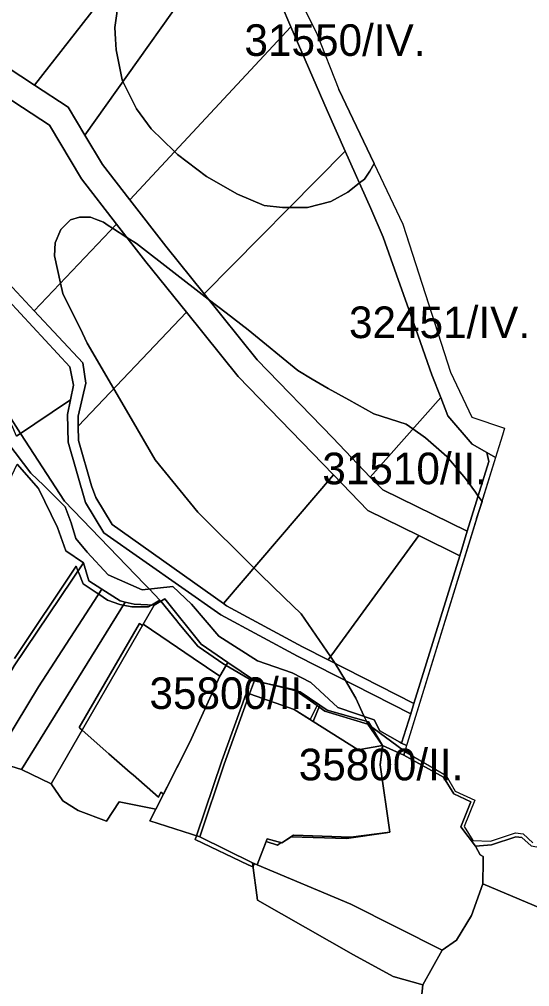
# Model space of a CAD drawing. Extents: x -522079 to -518792, y -1142400 to -1139961.
# Drawn here: x -519685.2 to -519443.2, y -1141371.1 to -1140912.1 of the extents above; entities that cross this region are included whole.
import ezdxf

# ---------------------------------------------------------------- set-up
doc = ezdxf.new("R2010")
doc.units = 0
for name, color, linetype in [('Hranice parcel', 7, 'Continuous'), ('Parcelní čísla', 7, 'Continuous'), ('Poz předměty', 7, 'Continuous'), ('Vnitřní kresba', 7, 'Continuous'), ('Značky bodu BP', 7, 'Continuous'), ('Značky budov', 7, 'Continuous'), ('Značky kultur', 7, 'Continuous')]:
    doc.layers.add(name, color=color, linetype=linetype)

msp = doc.modelspace()

# ---------------------------------------------------------------- linework, layer by layer
at = {"layer": 'Hranice parcel'}
for points in [[(-519569.14, -1140869.38), (-519544.31, -1140918.54), (-519533.66, -1140945.39), (-519503.31, -1141009.21), (-519480.71, -1141079.48), (-519470.66, -1141100.87), (-519455.06, -1141106.14), (-519456.05, -1141109.33), (-519457.77, -1141114.91), (-519459.37, -1141120.07), (-519463.51, -1141117.64), (-519470.4, -1141113.6), (-519481.95, -1141100.21), (-519485.33, -1141091.52), (-519489.53, -1141080.75), (-519497.19, -1141059.15), (-519506.32, -1141033.4), (-519512.69, -1141015.45), (-519518.48, -1141001.84), (-519530.67, -1140974.63), (-519539.28, -1140955.41), (-519556.41, -1140915.6), (-519561.03, -1140904.86)], [(-519697.68, -1140930.5), (-519678.04, -1140943.34), (-519662.03, -1140953.81), (-519654.13, -1140967.02), (-519645.74, -1140981.03), (-519632.87, -1140997.67), (-519615.79, -1141019.75), (-519597.55, -1141042.38), (-519572.39, -1141073.59), (-519536.59, -1141110.65), (-519518.89, -1141129.28), (-519512.81, -1141135.27), (-519472.79, -1141154.97), (-519476.38, -1141166.58), (-519495.79, -1141157.02), (-519519.99, -1141145.11), (-519536.28, -1141128.25), (-519581.39, -1141081.54), (-519605.96, -1141051.06), (-519625.22, -1141027.17), (-519639.1, -1141009.23), (-519655.67, -1140987.81), (-519670.91, -1140962.34), (-519692.38, -1140948.3)], [(-519704.97, -1141021.67), (-519678.16, -1141050.41), (-519655.12, -1141075.09), (-519653.67, -1141084.78), (-519657.33, -1141100.32), (-519657.23, -1141105.11), (-519657.08, -1141111.95), (-519650.97, -1141133.45), (-519648.88, -1141138.93), (-519641.2, -1141151.84), (-519588.4, -1141189.29), (-519586.93, -1141190.33), (-519550.99, -1141209.75), (-519538.78, -1141215.99), (-519498.1, -1141236.79), (-519499.59, -1141241.58), (-519553.27, -1141214.2), (-519589.6, -1141194.6), (-519645.14, -1141155.67), (-519653.82, -1141141.35), (-519662.06, -1141112.71), (-519662.35, -1141099.54), (-519660.92, -1141092.62), (-519659.49, -1141085.69), (-519661.22, -1141076.98), (-519702.3, -1141032.7)], [(-519686.59, -1141109.94), (-519660.92, -1141092.62), (-519662.35, -1141099.54), (-519662.06, -1141112.71), (-519653.82, -1141141.35), (-519645.14, -1141155.67), (-519589.6, -1141194.6), (-519553.27, -1141214.2), (-519499.59, -1141241.58), (-519503.9, -1141255.56), (-519504.82, -1141255.11), (-519514.28, -1141249.74), (-519516.96, -1141244.4), (-519534.2, -1141238.58), (-519546.94, -1141226.78), (-519555.86, -1141222.18), (-519572.33, -1141216.46), (-519590.58, -1141204.82), (-519603.54, -1141189.56), (-519612.48, -1141181.23), (-519626.9, -1141182.72), (-519643.13, -1141175.65), (-519653.03, -1141164.92), (-519658.41, -1141158.35), (-519660.65, -1141151.03), (-519663.4, -1141143.35), (-519673.55, -1141133.3), (-519679.71, -1141127.39), (-519690.7, -1141113)]]:
    msp.add_lwpolyline(points, dxfattribs=at)
msp.add_lwpolyline([(-519524.47, -1141258.63), (-519545.8, -1141245.26), (-519542.77, -1141237.45), (-519539.27, -1141239.84), (-519519.64, -1141245.38), (-519512.96, -1141256.69)], close=True, dxfattribs=at)
at = {"layer": 'Parcelní čísla'}
for points in [[(-519758.42, -1140883.91), (-519698.98, -1140816.54), (-519677.02, -1140829.78), (-519655.55, -1140840.89), (-519633.63, -1140850.83), (-519613.39, -1140860.38), (-519678.04, -1140943.34), (-519697.68, -1140930.5)], [(-519654.13, -1140967.02), (-519587.52, -1140873.31), (-519580.34, -1140878), (-519573.15, -1140884.93), (-519566.48, -1140893.71), (-519561.03, -1140904.86), (-519556.41, -1140915.6), (-519632.87, -1140997.67), (-519645.74, -1140981.03)], [(-519530.67, -1140974.63), (-519597.55, -1141042.38), (-519615.79, -1141019.75), (-519632.87, -1140997.67), (-519556.41, -1140915.6), (-519539.28, -1140955.41)], [(-519692.38, -1140948.3), (-519670.91, -1140962.34), (-519655.67, -1140987.81), (-519639.1, -1141009.23), (-519678.16, -1141050.41), (-519704.97, -1141021.67), (-519737.76, -1141001.71), (-519738.84, -1141001.14)], [(-519597.55, -1141042.38), (-519530.67, -1140974.63), (-519518.48, -1141001.84), (-519512.69, -1141015.45), (-519506.32, -1141033.4), (-519497.19, -1141059.15), (-519489.53, -1141080.75), (-519485.33, -1141091.52), (-519518.89, -1141129.28), (-519536.59, -1141110.65), (-519572.39, -1141073.59)], [(-519678.16, -1141050.41), (-519639.1, -1141009.23), (-519625.22, -1141027.17), (-519605.96, -1141051.06), (-519657.23, -1141105.11), (-519657.33, -1141100.32), (-519653.67, -1141084.78), (-519655.12, -1141075.09)], [(-519605.96, -1141051.06), (-519581.39, -1141081.54), (-519536.28, -1141128.25), (-519588.4, -1141189.29), (-519641.2, -1141151.84), (-519648.88, -1141138.93), (-519650.97, -1141133.45), (-519657.08, -1141111.95), (-519657.23, -1141105.11)], [(-519462.56, -1141121.92), (-519472.79, -1141154.97), (-519512.81, -1141135.27), (-519518.89, -1141129.28), (-519485.33, -1141091.52), (-519481.95, -1141100.21), (-519470.4, -1141113.6), (-519463.51, -1141117.64)], [(-519588.4, -1141189.29), (-519536.28, -1141128.25), (-519519.99, -1141145.11), (-519495.79, -1141157.02), (-519538.78, -1141215.99), (-519550.99, -1141209.75), (-519586.93, -1141190.33)], [(-519476.38, -1141166.58), (-519498.1, -1141236.79), (-519538.78, -1141215.99), (-519495.79, -1141157.02)]]:
    msp.add_lwpolyline(points, close=True, dxfattribs=at)
at = {"layer": 'Poz předměty'}
for points in [[(-519587.52, -1140873.31), (-519654.13, -1140967.02), (-519662.03, -1140953.81), (-519678.04, -1140943.34), (-519613.39, -1140860.38), (-519591.11, -1140871.05)], [(-519555.19, -1141299.24), (-519560.68, -1141302.79), (-519567.64, -1141300.94), (-519572.4, -1141313.2), (-519574.58, -1141312.28), (-519599.57, -1141299.96), (-519588.13, -1141265.46), (-519575.99, -1141232.08), (-519554.92, -1141239.55), (-519545.8, -1141245.26), (-519524.47, -1141258.63), (-519512.96, -1141256.69), (-519514.13, -1141265.79), (-519509.48, -1141297.81), (-519527.97, -1141300.15)]]:
    msp.add_lwpolyline(points, close=True, dxfattribs=at)
at = {"layer": 'Vnitřní kresba'}
for points in [[(-519690.7, -1141113), (-519679.71, -1141127.39), (-519673.55, -1141133.3), (-519663.4, -1141143.35), (-519660.65, -1141151.03), (-519658.41, -1141158.35), (-519653.03, -1141164.92), (-519643.13, -1141175.65), (-519626.9, -1141182.72), (-519612.48, -1141181.23), (-519603.54, -1141189.56), (-519590.58, -1141204.82), (-519572.33, -1141216.46), (-519555.86, -1141222.18), (-519546.94, -1141226.78), (-519534.2, -1141238.58), (-519516.96, -1141244.4), (-519514.28, -1141249.74), (-519504.82, -1141255.11), (-519503.9, -1141255.56), (-519501.64, -1141256.67), (-519502.46, -1141259.44), (-519502.94, -1141261.24), (-519512.96, -1141256.69), (-519519.64, -1141245.38), (-519539.27, -1141239.84), (-519542.77, -1141237.45), (-519552.03, -1141231.12), (-519573.7, -1141225.77), (-519586.25, -1141217.21), (-519599.05, -1141208.49), (-519616.23, -1141186.99), (-519621.3, -1141190.09), (-519630.7, -1141189.62), (-519635, -1141188.59), (-519637.37, -1141188.02), (-519646.01, -1141182.51), (-519652.19, -1141178.57), (-519654.81, -1141169.94), (-519663.19, -1141164.28), (-519667.13, -1141153.28), (-519676.06, -1141134.77), (-519686.19, -1141123.12)], [(-519442.41, -1141304.27), (-519446.9, -1141300.29), (-519449.71, -1141299.98), (-519461.31, -1141303.85), (-519468.94, -1141304.33), (-519475.87, -1141295.24), (-519471.1, -1141283.41), (-519479.21, -1141279.64), (-519484.08, -1141271.62), (-519502.94, -1141261.24), (-519502.46, -1141259.44), (-519482.78, -1141270.88), (-519478.58, -1141278.28), (-519469.18, -1141282.65), (-519474.2, -1141295.1), (-519470.14, -1141301.74), (-519461.74, -1141302), (-519449.98, -1141298.09), (-519446.22, -1141298.48), (-519441.7, -1141302.87)]]:
    msp.add_lwpolyline(points, dxfattribs=at)
msp.add_lwpolyline([(-519462.56, -1141121.92), (-519463.51, -1141117.64), (-519459.37, -1141120.07), (-519501.33, -1141255.67), (-519501.64, -1141256.67), (-519503.9, -1141255.56), (-519499.59, -1141241.58), (-519498.1, -1141236.79), (-519476.38, -1141166.58), (-519472.79, -1141154.97)], close=True, dxfattribs=at)
at = {"layer": 'Značky bodu BP'}
for points in [[(-519569.14, -1140869.38), (-519544.31, -1140918.54), (-519533.66, -1140945.39), (-519516.96, -1140980.51), (-519518.95, -1140984.06), (-519521.57, -1140987.86), (-519523.9, -1140989.74), (-519524.88, -1140990.52), (-519529.4, -1140994.15), (-519537.54, -1140998.54), (-519548.5, -1141001.37), (-519557.07, -1141001.37), (-519560.4, -1141001.37), (-519569.16, -1141000.43), (-519581.69, -1140995.09), (-519596.41, -1140986.61), (-519610.19, -1140976.25), (-519611.61, -1140974.85), (-519622.71, -1140964), (-519629.6, -1140954.57), (-519636.06, -1140941.6), (-519636.49, -1140940.75), (-519639.31, -1140926.61), (-519639.6, -1140921.53), (-519639.93, -1140915.93), (-519638.05, -1140902.43)], [(-519638.05, -1140902.43), (-519639.93, -1140915.93), (-519639.6, -1140921.53), (-519639.31, -1140926.61), (-519636.49, -1140940.75), (-519636.06, -1140941.6), (-519629.6, -1140954.57), (-519622.71, -1140964), (-519611.61, -1140974.85), (-519610.19, -1140976.25), (-519596.41, -1140986.61), (-519581.69, -1140995.09), (-519569.16, -1141000.43), (-519560.4, -1141001.37), (-519557.07, -1141001.37), (-519548.5, -1141001.37), (-519537.54, -1140998.54), (-519529.4, -1140994.15), (-519524.88, -1140990.52), (-519523.9, -1140989.74), (-519521.57, -1140987.86), (-519518.95, -1140984.06), (-519516.96, -1140980.51), (-519533.66, -1140945.39), (-519503.31, -1141009.21), (-519492.53, -1141042.73), (-519480.71, -1141079.48), (-519470.66, -1141100.87), (-519455.06, -1141106.14), (-519456.05, -1141109.33), (-519457.77, -1141114.91), (-519459.37, -1141120.07), (-519468.33, -1141149.01), (-519465.79, -1141140.81), (-519467.15, -1141139), (-519467.63, -1141138.31), (-519468.94, -1141136.48), (-519473.54, -1141130.01), (-519482.42, -1141119.57), (-519492.53, -1141110.66), (-519498.57, -1141106.42), (-519501.71, -1141104.21), (-519517.02, -1141099.29), (-519528.96, -1141092.71), (-519538.76, -1141087.32), (-519546.31, -1141082.8), (-519553.15, -1141078.71), (-519576.72, -1141059.36), (-519587.13, -1141051.34), (-519595.58, -1141044.83), (-519629.69, -1141018.52), (-519634.16, -1141015.62), (-519640.97, -1141011.2), (-519643.01, -1141009.87), (-519645.3, -1141008.38), (-519649.09, -1141006.86), (-519651.43, -1141005.93), (-519656.63, -1141005.93), (-519660.92, -1141007.16), (-519665.51, -1141011.76), (-519668.27, -1141018.21), (-519668.57, -1141024.35), (-519665.69, -1141037.26), (-519664.59, -1141042.17), (-519655.31, -1141061.04), (-519652.96, -1141065.82), (-519640.38, -1141087.34), (-519632.14, -1141101.44), (-519620.81, -1141121.1), (-519600.6, -1141145.98), (-519573.98, -1141172.41), (-519570.9, -1141175.46), (-519559.55, -1141186.49), (-519551.62, -1141194.2), (-519537.64, -1141214.42), (-519535.7, -1141217.23), (-519535.41, -1141217.71), (-519530.59, -1141225.77), (-519525.59, -1141234.12), (-519521.78, -1141242.52), (-519521.65, -1141242.82), (-519520.61, -1141245.1), (-519520.44, -1141245.48), (-519519.93, -1141246.59), (-519540.28, -1141240.34), (-519543.11, -1141238.33), (-519543.97, -1141237.72), (-519553.9, -1141230.66), (-519554.03, -1141230.56), (-519554.4, -1141230.29), (-519563.68, -1141228.24), (-519573.78, -1141226), (-519575.01, -1141225.73), (-519587.11, -1141218.63), (-519588.75, -1141217.67), (-519599.88, -1141209.94), (-519600.53, -1141209.49), (-519609.5, -1141198.7), (-519609.98, -1141198.13), (-519610.5, -1141197.51), (-519618.13, -1141188.15), (-519618.57, -1141187.61), (-519623.62, -1141182.38), (-519625.86, -1141180.06), (-519663.82, -1141140.73), (-519684.63, -1141108.61), (-519698.14, -1141087.76)], [(-519698.14, -1141087.76), (-519684.63, -1141108.61), (-519663.82, -1141140.73), (-519625.86, -1141180.06), (-519623.62, -1141182.38), (-519618.57, -1141187.61), (-519622.57, -1141190.02), (-519623.97, -1141190.87), (-519631.88, -1141190.86), (-519635.9, -1141190.04), (-519637.58, -1141189.69), (-519643.39, -1141187.64), (-519647.55, -1141184.87), (-519648.76, -1141184.06), (-519654.98, -1141179.93), (-519657.04, -1141174.68), (-519657.39, -1141173.78), (-519658.25, -1141171.6), (-519687.52, -1141215.32)], [(-519687.52, -1141215.32), (-519658.25, -1141171.6), (-519657.39, -1141173.78), (-519657.04, -1141174.68), (-519654.98, -1141179.93), (-519648.76, -1141184.06), (-519647.55, -1141184.87), (-519643.39, -1141187.64), (-519637.58, -1141189.69), (-519635.9, -1141190.04), (-519631.88, -1141190.86), (-519623.97, -1141190.87), (-519622.57, -1141190.02), (-519618.57, -1141187.61), (-519618.13, -1141188.15), (-519610.5, -1141197.51), (-519609.98, -1141198.13), (-519609.5, -1141198.7), (-519600.53, -1141209.49), (-519599.88, -1141209.94), (-519588.75, -1141217.67), (-519587.11, -1141218.63), (-519575.01, -1141225.73), (-519573.78, -1141226), (-519563.68, -1141228.24), (-519554.4, -1141230.29), (-519554.03, -1141230.56), (-519553.9, -1141230.66), (-519543.97, -1141237.72), (-519547.36, -1141244.28), (-519554.92, -1141239.55), (-519575.99, -1141232.08), (-519576.31, -1141232.95), (-519577.81, -1141232.43), (-519589.22, -1141263.89), (-519601.17, -1141299.45), (-519601.76, -1141301.21), (-519576.76, -1141313.26), (-519574.4, -1141314.26), (-519574.34, -1141314.1), (-519573.79, -1141312.61), (-519572.4, -1141313.2), (-519568.11, -1141302.15), (-519562.8, -1141303.9), (-519560.96, -1141302.71), (-519560.68, -1141302.79), (-519556.3, -1141299.95), (-519530.07, -1141300.79), (-519511.43, -1141298.06), (-519511.23, -1141298.03), (-519509.48, -1141297.81), (-519514.13, -1141265.79), (-519513.04, -1141257.34), (-519512.96, -1141256.69), (-519519.93, -1141246.59), (-519503.16, -1141258.92), (-519502.46, -1141259.44), (-519482.78, -1141270.88), (-519478.58, -1141278.28), (-519469.18, -1141282.65), (-519474.2, -1141295.1), (-519470.14, -1141301.74), (-519461.74, -1141302), (-519449.98, -1141298.09), (-519446.22, -1141298.48), (-519441.7, -1141302.87)]]:
    msp.add_lwpolyline(points, dxfattribs=at)
for points in [[(-519501.33, -1141255.67), (-519501.64, -1141256.67), (-519502.46, -1141259.44), (-519503.16, -1141258.92), (-519519.93, -1141246.59), (-519520.44, -1141245.48), (-519520.61, -1141245.1), (-519521.65, -1141242.82), (-519521.78, -1141242.52), (-519525.59, -1141234.12), (-519530.59, -1141225.77), (-519535.41, -1141217.71), (-519535.7, -1141217.23), (-519537.64, -1141214.42), (-519551.62, -1141194.2), (-519559.55, -1141186.49), (-519570.9, -1141175.46), (-519573.98, -1141172.41), (-519600.6, -1141145.98), (-519620.81, -1141121.1), (-519632.14, -1141101.44), (-519640.38, -1141087.34), (-519652.96, -1141065.82), (-519655.31, -1141061.04), (-519664.59, -1141042.17), (-519665.69, -1141037.26), (-519668.57, -1141024.35), (-519668.27, -1141018.21), (-519665.51, -1141011.76), (-519660.92, -1141007.16), (-519656.63, -1141005.93), (-519651.43, -1141005.93), (-519649.09, -1141006.86), (-519645.3, -1141008.38), (-519643.01, -1141009.87), (-519640.97, -1141011.2), (-519634.16, -1141015.62), (-519629.69, -1141018.52), (-519595.58, -1141044.83), (-519587.13, -1141051.34), (-519576.72, -1141059.36), (-519553.15, -1141078.71), (-519546.31, -1141082.8), (-519538.76, -1141087.32), (-519528.96, -1141092.71), (-519517.02, -1141099.29), (-519501.71, -1141104.21), (-519498.57, -1141106.42), (-519492.53, -1141110.66), (-519482.42, -1141119.57), (-519473.54, -1141130.01), (-519468.94, -1141136.48), (-519467.63, -1141138.31), (-519467.15, -1141139), (-519465.79, -1141140.81), (-519468.33, -1141149.01)], [(-519628.29, -1141198.7), (-519626.84, -1141199.71), (-519626.51, -1141199.14), (-519614.16, -1141207.48), (-519602.83, -1141215.13), (-519590.16, -1141223.69), (-519604.3, -1141255.01), (-519616.91, -1141279.74), (-519618.04, -1141278.78), (-519619.23, -1141281.17), (-519631.3, -1141270.6), (-519632.69, -1141269.38), (-519642.73, -1141260.59), (-519644.11, -1141259.38), (-519655.44, -1141249.39), (-519656.54, -1141248.43), (-519656.82, -1141248.18)], [(-519628.29, -1141198.7), (-519656.82, -1141248.18), (-519656.54, -1141248.43), (-519655.44, -1141249.39), (-519644.11, -1141259.38), (-519642.73, -1141260.59), (-519632.69, -1141269.38), (-519631.3, -1141270.6), (-519619.23, -1141281.17), (-519618.04, -1141278.78), (-519616.91, -1141279.74), (-519604.3, -1141255.01), (-519590.16, -1141223.69), (-519602.83, -1141215.13), (-519614.16, -1141207.48), (-519626.51, -1141199.14), (-519626.84, -1141199.71)], [(-519543.97, -1141237.72), (-519543.11, -1141238.33), (-519540.28, -1141240.34), (-519519.93, -1141246.59), (-519512.96, -1141256.69), (-519513.04, -1141257.34), (-519514.13, -1141265.79), (-519509.48, -1141297.81), (-519511.23, -1141298.03), (-519511.43, -1141298.06), (-519530.07, -1141300.79), (-519556.3, -1141299.95), (-519560.68, -1141302.79), (-519560.96, -1141302.71), (-519562.8, -1141303.9), (-519568.11, -1141302.15), (-519572.4, -1141313.2), (-519573.79, -1141312.61), (-519574.34, -1141314.1), (-519574.4, -1141314.26), (-519576.76, -1141313.26), (-519601.76, -1141301.21), (-519601.17, -1141299.45), (-519589.22, -1141263.89), (-519577.81, -1141232.43), (-519576.31, -1141232.95), (-519575.99, -1141232.08), (-519554.92, -1141239.55), (-519547.36, -1141244.28)]]:
    msp.add_lwpolyline(points, close=True, dxfattribs=at)
at = {"layer": 'Značky budov'}
for points in [[(-519687.67, -1141218.86), (-519709.65, -1141256.63), (-519720.8, -1141249.93), (-519714.2, -1141233.06), (-519705.26, -1141212.3), (-519728.23, -1141211.06), (-519688.75, -1141128.51), (-519686.19, -1141123.12), (-519676.06, -1141134.77), (-519667.13, -1141153.28), (-519663.19, -1141164.28), (-519654.81, -1141169.94)], [(-519697.46, -1141263.95), (-519709.65, -1141256.63), (-519687.67, -1141218.86), (-519654.81, -1141169.94), (-519652.19, -1141178.57), (-519646.01, -1141182.51), (-519676.14, -1141228.74)], [(-519635, -1141188.59), (-519684.2, -1141268.01), (-519697.46, -1141263.95), (-519676.14, -1141228.74), (-519646.01, -1141182.51), (-519637.37, -1141188.02)], [(-519670.06, -1141274.78), (-519621.3, -1141190.09), (-519616.23, -1141186.99), (-519599.05, -1141208.49), (-519586.25, -1141217.21), (-519590.16, -1141223.69), (-519604.3, -1141255.01), (-519620.55, -1141286.87), (-519637.83, -1141283.43), (-519643.91, -1141292.54), (-519657.26, -1141287.51), (-519664.55, -1141282.82)], [(-519684.2, -1141268.01), (-519635, -1141188.59), (-519630.7, -1141189.62), (-519621.3, -1141190.09), (-519670.06, -1141274.78)], [(-519620.55, -1141286.87), (-519604.3, -1141255.01), (-519590.16, -1141223.69), (-519586.25, -1141217.21), (-519573.7, -1141225.77), (-519575.99, -1141232.08), (-519588.13, -1141265.46), (-519599.57, -1141299.96), (-519623.35, -1141292.36)], [(-519554.92, -1141239.55), (-519575.99, -1141232.08), (-519573.7, -1141225.77), (-519552.03, -1141231.12), (-519542.77, -1141237.45), (-519545.8, -1141245.26)], [(-519470.8, -1141337.38), (-519477.91, -1141348.96), (-519484.66, -1141353.81), (-519528.06, -1141331.89), (-519572.4, -1141313.2), (-519567.64, -1141300.94), (-519560.68, -1141302.79), (-519555.19, -1141299.24), (-519527.97, -1141300.15), (-519509.48, -1141297.81), (-519514.13, -1141265.79), (-519512.96, -1141256.69), (-519502.94, -1141261.24), (-519484.08, -1141271.62), (-519479.21, -1141279.64), (-519471.1, -1141283.41), (-519475.87, -1141295.24), (-519468.94, -1141304.33), (-519466.74, -1141308.54), (-519465.25, -1141309.34), (-519465.26, -1141311.18), (-519465.42, -1141322.27)], [(-519385.2, -1141356.16), (-519465.42, -1141322.27), (-519465.26, -1141311.18), (-519465.25, -1141309.34), (-519466.74, -1141308.54), (-519468.94, -1141304.33), (-519461.31, -1141303.85), (-519449.71, -1141299.98), (-519446.9, -1141300.29), (-519442.41, -1141304.27), (-519431.85, -1141306.14), (-519427.38, -1141312.36), (-519420.99, -1141316.12), (-519419.15, -1141315.48), (-519371.28, -1141333.68)], [(-519528.06, -1141331.89), (-519484.66, -1141353.81), (-519493.9, -1141370.24), (-519507.9, -1141366.28), (-519526.67, -1141356.01), (-519572.25, -1141330.06), (-519574.58, -1141312.28), (-519572.4, -1141313.2)], [(-519494.92, -1141380.6), (-519493.9, -1141370.24), (-519484.66, -1141353.81), (-519477.91, -1141348.96), (-519470.8, -1141337.38), (-519465.42, -1141322.27), (-519385.2, -1141356.16), (-519392.16, -1141399.31), (-519386.73, -1141417.35), (-519402.53, -1141416.1), (-519450.75, -1141420.94), (-519466.91, -1141416.21), (-519490.7, -1141404.57), (-519496.45, -1141402.69), (-519489.99, -1141393.96), (-519488.36, -1141388.76)]]:
    msp.add_lwpolyline(points, close=True, dxfattribs=at)
msp.add_lwpolyline([(-519697.46, -1141263.95), (-519684.2, -1141268.01), (-519670.06, -1141274.78), (-519664.55, -1141282.82), (-519657.26, -1141287.51), (-519643.91, -1141292.54), (-519637.83, -1141283.43), (-519620.55, -1141286.87), (-519623.35, -1141292.36), (-519599.57, -1141299.96), (-519574.58, -1141312.28), (-519572.25, -1141330.06), (-519526.67, -1141356.01), (-519507.9, -1141366.28), (-519493.9, -1141370.24), (-519494.92, -1141380.6)], dxfattribs=at)
at = {"layer": 'Značky kultur'}
msp.add_lwpolyline([(-519702.3, -1141032.7), (-519661.22, -1141076.98), (-519659.49, -1141085.69), (-519660.92, -1141092.62), (-519686.59, -1141109.94), (-519688.8, -1141104.67), (-519698.11, -1141093.5), (-519702.87, -1141087.27), (-519704.67, -1141084.75), (-519705.02, -1141083.87), (-519715.52, -1141069.7), (-519725.48, -1141067.48)], close=True, dxfattribs=at)

# ---------------------------------------------------------------- texts
at = {"layer": 'Značky bodu BP'}
for s, p in [('31550/IV.', (-519578.45, -1140929.45)), ('32451/IV.', (-519528.87, -1141063.35)), ('31510/II.', (-519541.52, -1141132.69)), ('35800/II.', (-519623.49, -1141239.31)), ('35800/II.', (-519552.7, -1141273.17))]:
    msp.add_text(s, height=15, rotation=360, dxfattribs=at).set_placement(p)

doc.saveas('drawing.dxf')
